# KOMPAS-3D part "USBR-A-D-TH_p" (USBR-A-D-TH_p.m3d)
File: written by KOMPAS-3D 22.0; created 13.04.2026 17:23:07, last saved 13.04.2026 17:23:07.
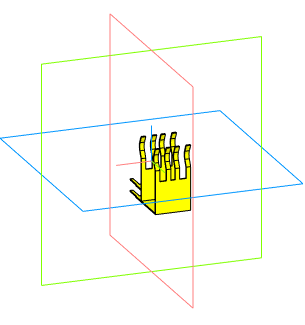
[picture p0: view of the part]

Document properties: Автор: Andrey; Полное имя файла: C:\Users\User1\Documents\USBR-A-D-TH_p.m3d

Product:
- Part/product: USBR-A-D-TH_p
    Комментарий: USBR-A-D-TH_p

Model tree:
1. Операция без истории:1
